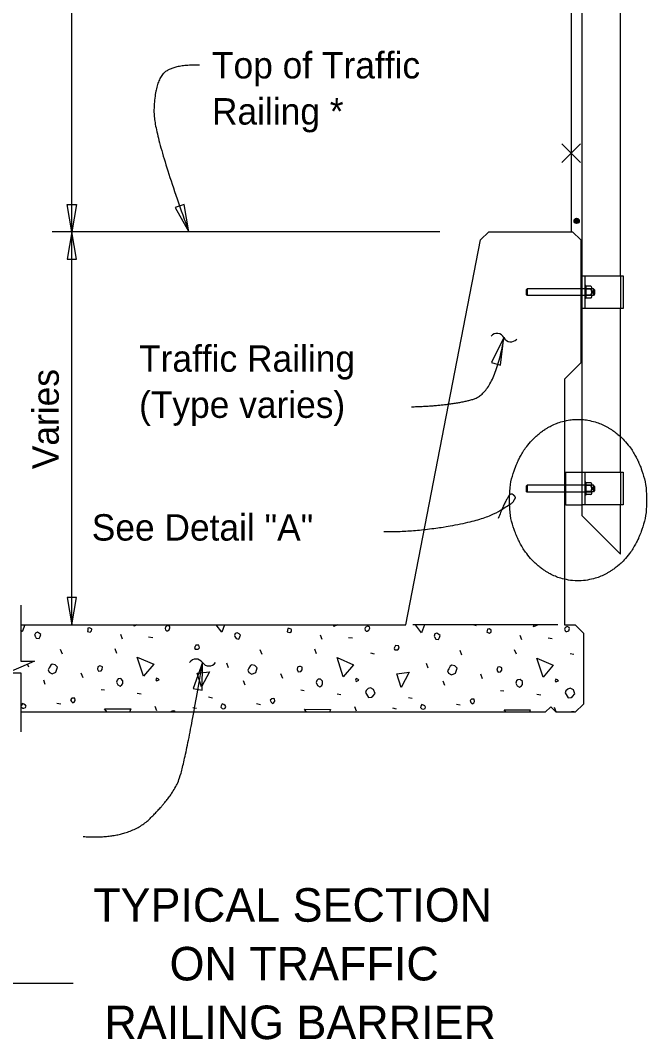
# Model space of a CAD drawing. Extents: x 0.2 to 40.8, y 0.5 to 25.7.
# Drawn here: x 29.01 to 33.79, y 11.06 to 18.84 of the extents above; entities that cross this region are included whole.
import ezdxf

# ---------------------------------------------------------------- set-up
doc = ezdxf.new("R2010")
doc.units = 0
for name, color, linetype in [('Dimension', 7, 'Continuous'), ('Miscellaneous', 7, 'Continuous'), ('SteelMisc', 7, 'Continuous'), ('SteelMisc_h', 7, 'Continuous'), ('SupstrConc', 7, 'Continuous'), ('SupstrConc_h', 7, 'Continuous'), ('TextStructures', 7, 'Continuous'), ('TrafBarrierConc', 7, 'Continuous')]:
    doc.layers.add(name, color=color, linetype=linetype)

msp = doc.modelspace()

# ---------------------------------------------------------------- linework, layer by layer
at = {"layer": 'Dimension'}
for p, q in [((29.4061, 14.2246), (29.4061, 23.2246)), ((32.214, 17.2246), (29.2561, 17.2246)), ((23.6151, 11.4901), (29.4153, 11.4901))]:
    msp.add_line(p, q, dxfattribs=at)
for points in [[(29.4061, 17.2246), (29.3708, 17.4328), (29.4413, 17.4328)], [(30.2977, 17.2246), (30.2616, 17.4327), (30.1951, 17.4092)], [(29.4061, 17.2246), (29.3708, 17.0163), (29.4413, 17.0163)], [(32.7026, 16.4167), (32.6085, 16.2276), (32.676, 16.2071)], [(29.4061, 14.2246), (29.4413, 14.4328), (29.3708, 14.4328)], [(30.403, 13.937), (30.3312, 13.7384), (30.4006, 13.7258)]]:
    msp.add_lwpolyline(points, close=True, dxfattribs=at)
msp.add_lwpolyline([(29.0176, 14.3746), (29.0176, 13.9474), (29.1209, 13.9474), (29.0176, 13.9024), (28.9142, 13.8574), (29.0176, 13.8574), (29.0176, 13.4079)], dxfattribs=at)
for centre, start, end in [((32.6489, 16.3894), 27.32823, 139.05545), ((32.7548, 16.4441), 207.32823, 319.05545), ((30.3527, 13.9038), 33.91896, 145.64618), ((30.4517, 13.9703), 213.91896, 325.64618)]:
    msp.add_arc(centre, 0.0596, start, end, dxfattribs=at)
for points, degree in [([(30.3802, 18.496), (30.1383, 18.5019), (30.0322, 18.3129), (30.0322, 17.9586), (30.2976, 17.2245)], 2), ([(31.9983, 15.889), (32.2959, 15.8977), (32.6322, 15.993), (32.7026, 16.4166)], 2), ([(33.2678, 14.5608), (33.3028, 14.5608), (33.3375, 14.5649), (33.4054, 14.5811), (33.4386, 14.5931), (33.4864, 14.6167), (33.502, 14.6255), (33.5248, 14.64), (33.5323, 14.6451), (33.5471, 14.6557), (33.5543, 14.6612), (33.5899, 14.6896), (33.6163, 14.7155), (33.6642, 14.7726), (33.6856, 14.8038), (33.7091, 14.8457), (33.7136, 14.8542), (33.7223, 14.8715), (33.7265, 14.8803), (33.7384, 14.9069), (33.7456, 14.9251), (33.7776, 15.0175), (33.7909, 15.0966), (33.7909, 15.2569), (33.7776, 15.336), (33.7456, 15.4283), (33.7384, 15.4465), (33.7265, 15.4731), (33.7223, 15.4819), (33.7136, 15.4992), (33.7091, 15.5077), (33.6856, 15.5496), (33.6642, 15.5808), (33.6163, 15.638), (33.5899, 15.6638), (33.5543, 15.6923), (33.5471, 15.6978), (33.5323, 15.7083), (33.5248, 15.7134), (33.502, 15.7279), (33.4864, 15.7367), (33.4386, 15.7603), (33.4054, 15.7724), (33.3375, 15.7885), (33.3028, 15.7926), (33.2328, 15.7926), (33.198, 15.7885), (33.1301, 15.7724), (33.097, 15.7603), (33.0492, 15.7367), (33.0336, 15.7279), (33.0108, 15.7134), (33.0033, 15.7083), (32.9885, 15.6978), (32.9812, 15.6923), (32.9456, 15.6638), (32.9193, 15.638), (32.8714, 15.5808), (32.8499, 15.5496), (32.8264, 15.5077), (32.8219, 15.4992), (32.8132, 15.4819), (32.8091, 15.4731), (32.7971, 15.4465), (32.79, 15.4283), (32.7579, 15.336), (32.7447, 15.2569), (32.7447, 15.0966), (32.7579, 15.0175), (32.79, 14.9251), (32.7971, 14.9069), (32.8091, 14.8803), (32.8132, 14.8715), (32.8219, 14.8542), (32.8264, 14.8457), (32.8499, 14.8038), (32.8714, 14.7726), (32.9193, 14.7155), (32.9456, 14.6896), (32.9812, 14.6612), (32.9885, 14.6557), (33.0033, 14.6451), (33.0108, 14.64), (33.0336, 14.6255), (33.0492, 14.6167), (33.097, 14.5931), (33.1301, 14.5811), (33.198, 14.5649), (33.2328, 14.5608), (33.2678, 14.5608)], 3), ([(31.785, 14.9372), (32.0075, 14.9325), (32.5443, 15.0224), (32.7693, 15.1547), (32.78, 15.1766), (32.7962, 15.2026), (32.737, 15.2403), (32.6589, 15.0361)], 2), ([(29.4916, 12.6094), (29.8372, 12.5861), (30.1609, 12.9013), (30.2688, 13.1436), (30.4029, 13.9374)], 2)]:
    msp.add_open_spline(points, degree=degree, dxfattribs=at)
at = {"layer": 'Miscellaneous'}
for p, q in [((33.2861, 17.8952), (33.1447, 17.7539)), ((33.1447, 17.8952), (33.2861, 17.7539)), ((33.2884, 16.8894), (33.2988, 16.8894)), ((33.292, 16.8894), (33.292, 16.6394)), ((33.2953, 16.8894), (33.2953, 16.6394)), ((33.3795, 16.7756), (33.3795, 16.7548)), ((33.3891, 16.7756), (33.3891, 16.7548)), ((33.2988, 16.6394), (33.2884, 16.6394)), ((33.1634, 15.3894), (33.1738, 15.3894)), ((33.167, 15.3894), (33.167, 15.1394)), ((33.1703, 15.3894), (33.1703, 15.1394)), ((33.3795, 15.2756), (33.3795, 15.2548)), ((33.3891, 15.2756), (33.3891, 15.2548)), ((33.1738, 15.1394), (33.1634, 15.1394)), ((30.9661, 14.2246), (30.9674, 14.2243)), ((32.4722, 14.2246), (32.4912, 14.2207)), ((29.7919, 14.1165), (29.7795, 14.15)), ((29.9916, 14.1324), (30.0234, 14.1288)), ((31.3157, 14.1129), (31.3033, 14.1465)), ((31.5154, 14.1288), (31.5473, 14.1253)), ((32.8395, 14.1094), (32.8271, 14.143)), ((33.0392, 14.1253), (33.0711, 14.1218)), ((29.334, 14.0015), (29.3199, 14.0369)), ((29.7494, 14.0068), (29.7353, 14.0422)), ((30.8578, 13.998), (30.8437, 14.0334)), ((31.2732, 14.0033), (31.2591, 14.0387)), ((31.6834, 14.0104), (31.7117, 14.0033)), ((32.3816, 13.9945), (32.3675, 14.0298)), ((32.7971, 13.9998), (32.7829, 14.0351)), ((33.2072, 14.0068), (33.2355, 13.9998)), ((29.0777, 13.9008), (29.0682, 13.9245)), ((30.6015, 13.8972), (30.5874, 13.9326)), ((32.1253, 13.8937), (32.1112, 13.9291)), ((29.4913, 13.8195), (29.4772, 13.8548)), ((31.0152, 13.8159), (31.001, 13.8513)), ((32.539, 13.8124), (32.5248, 13.8477)), ((29.2032, 13.7682), (29.1908, 13.8018)), ((30.727, 13.7647), (30.7146, 13.7983)), ((32.2508, 13.7611), (32.2384, 13.7947)), ((29.6292, 13.7311), (29.654, 13.7275)), ((29.905, 13.7028), (29.935, 13.6975)), ((31.153, 13.7275), (31.1778, 13.724)), ((31.4288, 13.6993), (31.4589, 13.694)), ((32.6769, 13.724), (32.7016, 13.7205)), ((32.9526, 13.6957), (32.9827, 13.6904)), ((29.2916, 13.6268), (29.3216, 13.6215)), ((30.4495, 13.6745), (30.4778, 13.6674)), ((30.8154, 13.6232), (30.8454, 13.6179)), ((31.9733, 13.671), (32.0016, 13.6639)), ((32.3392, 13.6197), (32.3693, 13.6144)), ((30.0535, 13.5684), (30.0411, 13.602)), ((30.3275, 13.595), (30.3558, 13.5879)), ((31.5773, 13.5649), (31.5649, 13.5985)), ((31.8513, 13.5914), (31.8796, 13.5844)), ((33.1011, 13.5614), (33.0887, 13.595))]:
    msp.add_line(p, q, dxfattribs=at)
for points in [[(33.2155, 23.2246), (33.2155, 17.2246)], [(29.0264, 14.1713), (29.0176, 14.1829)], [(29.0463, 14.2246), (29.0264, 14.1713)], [(29.1254, 14.1394), (29.1343, 14.1235), (29.1555, 14.12), (29.1643, 14.1359), (29.1678, 14.15), (29.159, 14.1589), (29.1431, 14.1677), (29.1272, 14.1624), (29.1219, 14.1465), (29.1254, 14.1394)], [(29.5249, 14.1748), (29.5444, 14.1695), (29.5567, 14.1783), (29.5585, 14.1907), (29.555, 14.1942), (29.5408, 14.2013), (29.5285, 14.1995), (29.5267, 14.1872), (29.5249, 14.1748)], [(29.8802, 14.2154), (29.8831, 14.2246)], [(29.9005, 14.2246), (29.8802, 14.2154)], [(30.1277, 14.1801), (30.1348, 14.1801), (30.1489, 14.1872), (30.1543, 14.2031), (30.1525, 14.2119), (30.1383, 14.219), (30.1207, 14.2084), (30.1171, 14.1978), (30.1207, 14.1872), (30.1277, 14.1801)], [(30.5502, 14.1677), (30.507, 14.2246)], [(30.5715, 14.2246), (30.5502, 14.1677)], [(30.6492, 14.1359), (30.6581, 14.12), (30.6793, 14.1165), (30.6881, 14.1324), (30.6917, 14.1465), (30.6828, 14.1553), (30.6669, 14.1642), (30.651, 14.1589), (30.6457, 14.143), (30.6492, 14.1359)], [(31.0487, 14.1713), (31.0682, 14.1659), (31.0806, 14.1748), (31.0823, 14.1872), (31.0788, 14.1907), (31.0647, 14.1978), (31.0523, 14.196), (31.0505, 14.1836), (31.0487, 14.1713)], [(31.4041, 14.2119), (31.408, 14.2246)], [(31.4322, 14.2246), (31.4041, 14.2119)], [(31.6516, 14.1766), (31.6586, 14.1766), (31.6728, 14.1836), (31.6781, 14.1995), (31.6763, 14.2084), (31.6622, 14.2154), (31.6445, 14.2048), (31.6409, 14.1942), (31.6445, 14.1836), (31.6516, 14.1766)], [(32.074, 14.1642), (32.0282, 14.2246)], [(32.0966, 14.2246), (32.074, 14.1642)], [(32.173, 14.1324), (32.1819, 14.1165), (32.2031, 14.1129), (32.2119, 14.1288), (32.2155, 14.143), (32.2066, 14.1518), (32.1907, 14.1606), (32.1748, 14.1553), (32.1695, 14.1394), (32.173, 14.1324)], [(32.5726, 14.1677), (32.592, 14.1624), (32.6044, 14.1713), (32.6061, 14.1836), (32.6026, 14.1872), (32.5885, 14.1942), (32.5761, 14.1925), (32.5743, 14.1801), (32.5726, 14.1677)], [(32.9279, 14.2084), (32.9329, 14.2246)], [(32.9639, 14.2246), (32.9279, 14.2084)], [(33.1754, 14.173), (33.1824, 14.173), (33.1966, 14.1801), (33.2019, 14.196), (33.2001, 14.2048), (33.186, 14.2119), (33.1683, 14.2013), (33.1648, 14.1907), (33.1683, 14.1801), (33.1754, 14.173)], [(30.3469, 14.0387), (30.3682, 14.0387), (30.3788, 14.0493), (30.3735, 14.0687), (30.3505, 14.0705), (30.3469, 14.0599), (30.3416, 14.051), (30.3469, 14.0387), (30.3434, 14.0422)], [(31.8708, 14.0351), (31.892, 14.0351), (31.9026, 14.0457), (31.8973, 14.0652), (31.8743, 14.067), (31.8708, 14.0563), (31.8654, 14.0475), (31.8708, 14.0351), (31.8672, 14.0387)], [(29.9527, 13.8318), (29.905, 13.9786), (30.0305, 13.9238), (29.9527, 13.8318)], [(31.4765, 13.8283), (31.4288, 13.975), (31.5543, 13.9202), (31.4765, 13.8283)], [(33.0004, 13.8248), (32.9526, 13.9715), (33.0781, 13.9167), (33.0004, 13.8248)], [(29.2315, 13.8637), (29.2545, 13.8513), (29.2845, 13.8637), (29.2969, 13.9008), (29.2792, 13.9185), (29.2562, 13.9238), (29.2456, 13.9167), (29.2332, 13.8972), (29.2244, 13.8813), (29.2315, 13.8637)], [(29.6009, 13.8866), (29.6098, 13.8707), (29.6292, 13.8725), (29.6381, 13.8849), (29.6398, 13.9043), (29.6275, 13.9096), (29.6186, 13.9114), (29.608, 13.9079), (29.6045, 13.9043), (29.6009, 13.8866)], [(30.3947, 13.7505), (30.3611, 13.8548), (30.4548, 13.8672), (30.3947, 13.7505)], [(30.7553, 13.8601), (30.7783, 13.8477), (30.8083, 13.8601), (30.8207, 13.8972), (30.803, 13.9149), (30.78, 13.9202), (30.7694, 13.9132), (30.7571, 13.8937), (30.7482, 13.8778), (30.7553, 13.8601)], [(31.1248, 13.8831), (31.1336, 13.8672), (31.153, 13.869), (31.1619, 13.8813), (31.1636, 13.9008), (31.1513, 13.9061), (31.1424, 13.9079), (31.1318, 13.9043), (31.1283, 13.9008), (31.1248, 13.8831)], [(31.9185, 13.747), (31.8849, 13.8513), (31.9786, 13.8637), (31.9185, 13.747)], [(32.2791, 13.8566), (32.3021, 13.8442), (32.3321, 13.8566), (32.3445, 13.8937), (32.3268, 13.9114), (32.3039, 13.9167), (32.2932, 13.9096), (32.2809, 13.8902), (32.272, 13.8743), (32.2791, 13.8566)], [(32.6486, 13.8796), (32.6574, 13.8637), (32.6769, 13.8654), (32.6857, 13.8778), (32.6875, 13.8972), (32.6751, 13.9026), (32.6662, 13.9043), (32.6556, 13.9008), (32.6521, 13.8972), (32.6486, 13.8796)], [(29.7459, 13.7876), (29.7565, 13.7664), (29.7742, 13.7558), (29.7883, 13.7664), (29.7954, 13.777), (29.7954, 13.7983), (29.7795, 13.8142), (29.76, 13.8124), (29.7512, 13.8036), (29.7459, 13.7876)], [(30.0517, 13.7965), (30.0712, 13.8053), (30.0641, 13.8124), (30.0517, 13.8177), (30.0464, 13.8053), (30.0517, 13.7965)], [(31.2697, 13.7841), (31.2803, 13.7629), (31.298, 13.7523), (31.3121, 13.7629), (31.3192, 13.7735), (31.3192, 13.7947), (31.3033, 13.8106), (31.2839, 13.8089), (31.275, 13.8), (31.2697, 13.7841)], [(31.5755, 13.7929), (31.595, 13.8018), (31.5879, 13.8089), (31.5755, 13.8142), (31.5702, 13.8018), (31.5755, 13.7929)], [(32.7935, 13.7806), (32.8041, 13.7594), (32.8218, 13.7488), (32.836, 13.7594), (32.843, 13.77), (32.843, 13.7912), (32.8271, 13.8071), (32.8077, 13.8053), (32.7988, 13.7965), (32.7935, 13.7806)], [(33.0994, 13.7894), (33.1188, 13.7983), (33.1117, 13.8053), (33.0994, 13.8106), (33.094, 13.7983), (33.0994, 13.7894)], [(31.6462, 13.7081), (31.6692, 13.671), (31.6922, 13.6727), (31.701, 13.6816), (31.7205, 13.701), (31.7081, 13.7311), (31.6834, 13.7452), (31.6657, 13.7381), (31.6516, 13.724), (31.6462, 13.7081)], [(33.1701, 13.7046), (33.193, 13.6674), (33.216, 13.6692), (33.2249, 13.678), (33.2443, 13.6975), (33.2319, 13.7275), (33.2072, 13.7417), (33.1895, 13.7346), (33.1754, 13.7205), (33.1701, 13.7046)], [(29.0282, 13.5897), (29.0406, 13.5879), (29.0529, 13.5932), (29.0565, 13.6038), (29.0512, 13.6126), (29.0406, 13.6197), (29.0282, 13.625), (29.0211, 13.6109), (29.0176, 13.6003)], [(29.403, 13.6392), (29.4136, 13.6285), (29.4242, 13.6356), (29.4312, 13.6462), (29.4277, 13.6639), (29.4189, 13.6657), (29.4065, 13.6639), (29.3959, 13.6533), (29.403, 13.6392)], [(30.552, 13.5861), (30.5644, 13.5844), (30.5767, 13.5897), (30.5803, 13.6003), (30.575, 13.6091), (30.5644, 13.6162), (30.552, 13.6215), (30.5449, 13.6073), (30.5414, 13.5967), (30.552, 13.5861)], [(30.9268, 13.6356), (30.9374, 13.625), (30.948, 13.6321), (30.955, 13.6427), (30.9515, 13.6604), (30.9427, 13.6621), (30.9303, 13.6604), (30.9197, 13.6498), (30.9268, 13.6356)], [(32.0758, 13.5826), (32.0882, 13.5808), (32.1006, 13.5861), (32.1041, 13.5967), (32.0988, 13.6056), (32.0882, 13.6126), (32.0758, 13.6179), (32.0687, 13.6038), (32.0652, 13.5932), (32.0758, 13.5826)], [(32.4506, 13.6321), (32.4612, 13.6215), (32.4718, 13.6285), (32.4789, 13.6392), (32.4753, 13.6568), (32.4665, 13.6586), (32.4541, 13.6568), (32.4435, 13.6462), (32.4506, 13.6321)], [(29.0176, 13.6003), (29.0282, 13.5897)], [(29.6759, 13.5578), (29.6557, 13.5844), (29.8555, 13.5826), (29.8462, 13.5578)], [(30.1932, 13.5578), (30.1913, 13.5669), (30.1825, 13.5687), (30.1701, 13.5669), (30.161, 13.5578)], [(31.197, 13.5578), (31.1796, 13.5808), (31.3793, 13.579), (31.3714, 13.5578)], [(32.7181, 13.5578), (32.7034, 13.5773), (32.9031, 13.5755), (32.8965, 13.5578)], [(33.2394, 13.5578), (33.239, 13.5599), (33.2301, 13.5616), (33.2178, 13.5599), (33.2157, 13.5578)]]:
    msp.add_lwpolyline(points, dxfattribs=at)
at = {"layer": 'SteelMisc'}
for p, q in [((33.2155, 23.2245), (33.2155, 17.2245)), ((33.2988, 16.8894), (33.2988, 23.2245)), ((33.5905, 16.8894), (33.5905, 23.2245)), ((33.2988, 16.6394), (33.2988, 16.8894)), ((33.2988, 16.8894), (33.6113, 16.8894)), ((33.3197, 16.8894), (33.3197, 16.6394)), ((33.6113, 16.8894), (33.6113, 16.6394)), ((33.3267, 16.8141), (33.3197, 16.8141)), ((33.3267, 16.8141), (33.3267, 16.7147)), ((33.3644, 16.8098), (33.3267, 16.8098)), ((33.3267, 16.719), (33.3267, 16.8098)), ((33.3647, 16.7871), (33.3267, 16.7871)), ((33.3647, 16.7418), (33.3267, 16.7418)), ((33.3731, 16.7303), (33.3731, 16.7985)), ((33.3844, 16.7902), (33.3731, 16.7902)), ((33.3844, 16.7387), (33.3731, 16.7387)), ((33.3844, 16.7902), (33.3844, 16.7387)), ((33.394, 16.7805), (33.3844, 16.7902)), ((33.394, 16.75), (33.3844, 16.7387)), ((33.394, 16.7805), (33.394, 16.75)), ((33.3267, 16.7147), (33.3197, 16.7147)), ((33.3644, 16.719), (33.3267, 16.719)), ((33.2988, 15.0561), (33.2988, 16.6394)), ((33.6113, 16.6394), (33.2988, 16.6394)), ((33.5905, 15.3894), (33.5905, 16.6394)), ((33.1738, 15.1394), (33.1738, 15.3894)), ((33.1738, 15.3894), (33.2988, 15.3894)), ((33.2988, 15.3894), (33.6113, 15.3894)), ((33.3197, 15.3894), (33.3197, 15.1394)), ((33.6113, 15.3894), (33.6113, 15.1394)), ((33.3267, 15.3141), (33.3197, 15.3141)), ((33.3267, 15.3141), (33.3267, 15.2147)), ((33.3644, 15.3098), (33.3267, 15.3098)), ((33.3267, 15.219), (33.3267, 15.3098)), ((33.3647, 15.2871), (33.3267, 15.2871)), ((33.3731, 15.2303), (33.3731, 15.2985)), ((33.3844, 15.2902), (33.3731, 15.2902)), ((33.3844, 15.2902), (33.3844, 15.2387)), ((33.394, 15.2805), (33.3844, 15.2902)), ((33.394, 15.25), (33.3844, 15.2387)), ((33.394, 15.2805), (33.394, 15.25)), ((33.3267, 15.2147), (33.3197, 15.2147)), ((33.3647, 15.2418), (33.3267, 15.2418)), ((33.3644, 15.219), (33.3267, 15.219)), ((33.3844, 15.2387), (33.3731, 15.2387)), ((33.1738, 15.1394), (33.2988, 15.1394)), ((33.6113, 15.1394), (33.2988, 15.1394)), ((33.5905, 14.7644), (33.5905, 15.1394))]:
    msp.add_line(p, q, dxfattribs=at)
msp.add_lwpolyline([(33.2988, 15.0561), (33.5905, 14.7644)], dxfattribs=at)
for radius in [0.0197, 0.0172, 0.0147, 0.0122, 0.00975, 0.00725, 0.00475, 0.00225]:
    msp.add_circle((33.2572, 17.3079), radius, dxfattribs=at)
for centre, radius, start, end in [((33.3613, 16.7984), 0.0118, 286.59863, 74.70054), ((33.3613, 16.7304), 0.0118, 285.15064, 73.50417), ((33.3384, 16.7644), 0.0347, 319.20147, 40.79853), ((33.3613, 15.2984), 0.0118, 286.59863, 74.70054), ((33.3384, 15.2644), 0.0347, 319.20147, 40.79853), ((33.3613, 15.2304), 0.0118, 285.15064, 73.50417)]:
    msp.add_arc(centre, radius, start, end, dxfattribs=at)
at = {"layer": 'SteelMisc_h'}
for p, q in [((33.5905, 16.8894), (33.5905, 16.6394)), ((32.8799, 16.7904), (32.8717, 16.7822)), ((32.8717, 16.7822), (32.8717, 16.7465)), ((32.8799, 16.7384), (32.8717, 16.7465)), ((33.3731, 16.7904), (32.8799, 16.7904)), ((32.8799, 16.7904), (32.8799, 16.7384)), ((33.3731, 16.7384), (32.8799, 16.7384)), ((33.5905, 15.3894), (33.5905, 15.1394)), ((33.5905, 15.3894), (33.5905, 15.1394)), ((32.8799, 15.2904), (32.8717, 15.2822)), ((32.8717, 15.2822), (32.8717, 15.2465)), ((32.8799, 15.2384), (32.8717, 15.2465)), ((33.3731, 15.2904), (32.8799, 15.2904)), ((32.8799, 15.2904), (32.8799, 15.2384)), ((33.3731, 15.2384), (32.8799, 15.2384))]:
    msp.add_line(p, q, dxfattribs=at)
at = {"layer": 'SupstrConc'}
for p, q in [((29.0176, 14.2246), (31.9551, 14.2246)), ((33.1634, 14.2246), (33.2467, 14.2246)), ((33.2467, 14.2246), (33.3092, 14.1621)), ((33.3092, 14.1621), (33.3092, 13.6204)), ((33.3092, 13.6204), (33.2467, 13.5579)), ((33.0175, 13.5579), (29.0176, 13.5579)), ((33.0175, 13.5579), (33.0592, 13.5995)), ((33.0592, 13.5995), (33.1009, 13.5579)), ((33.2467, 13.5579), (33.1009, 13.5579))]:
    msp.add_line(p, q, dxfattribs=at)
at = {"layer": 'SupstrConc_h'}
msp.add_line((33.1124, 14.2246), (32.0061, 14.2246), dxfattribs=at)
at = {"layer": 'TrafBarrierConc'}
for p, q in [((32.5244, 17.162), (32.5869, 17.2245)), ((32.5869, 17.2245), (33.2259, 17.2246)), ((33.2259, 17.2245), (33.2884, 17.162)), ((31.9551, 14.2246), (32.5244, 17.162)), ((33.2884, 17.162), (33.2884, 16.2245)), ((33.2884, 16.2245), (33.1634, 16.0995)), ((33.1634, 16.0995), (33.1634, 14.2246))]:
    msp.add_line(p, q, dxfattribs=at)

# ---------------------------------------------------------------- texts
at = {"layer": 'Dimension'}
for s, height, p in [('Top of Traffic ', 0.2016, (30.4747, 18.3949)), ('Railing *', 0.2016, (30.4747, 18.0429)), ('Traffic Railing ', 0.2016, (29.9184, 16.1562)), ('(Type varies)', 0.2016, (29.9184, 15.8042)), ('TYPICAL SECTION', 0.256001, (29.5683, 11.9589)), ('ON TRAFFIC', 0.256, (30.1511, 11.5109)), ('RAILING BARRIER', 0.256001, (29.6545, 11.0629))]:
    msp.add_text(s, height=height, dxfattribs=at).set_placement(p)
at = {"layer": 'TextStructures'}
msp.add_text('Varies', height=0.2016, rotation=90, dxfattribs=at).set_placement((29.3061, 15.4127))
msp.add_text('See Detail "A"', height=0.2016, dxfattribs=at).set_placement((29.5575, 14.8677))

doc.saveas('drawing.dxf')
